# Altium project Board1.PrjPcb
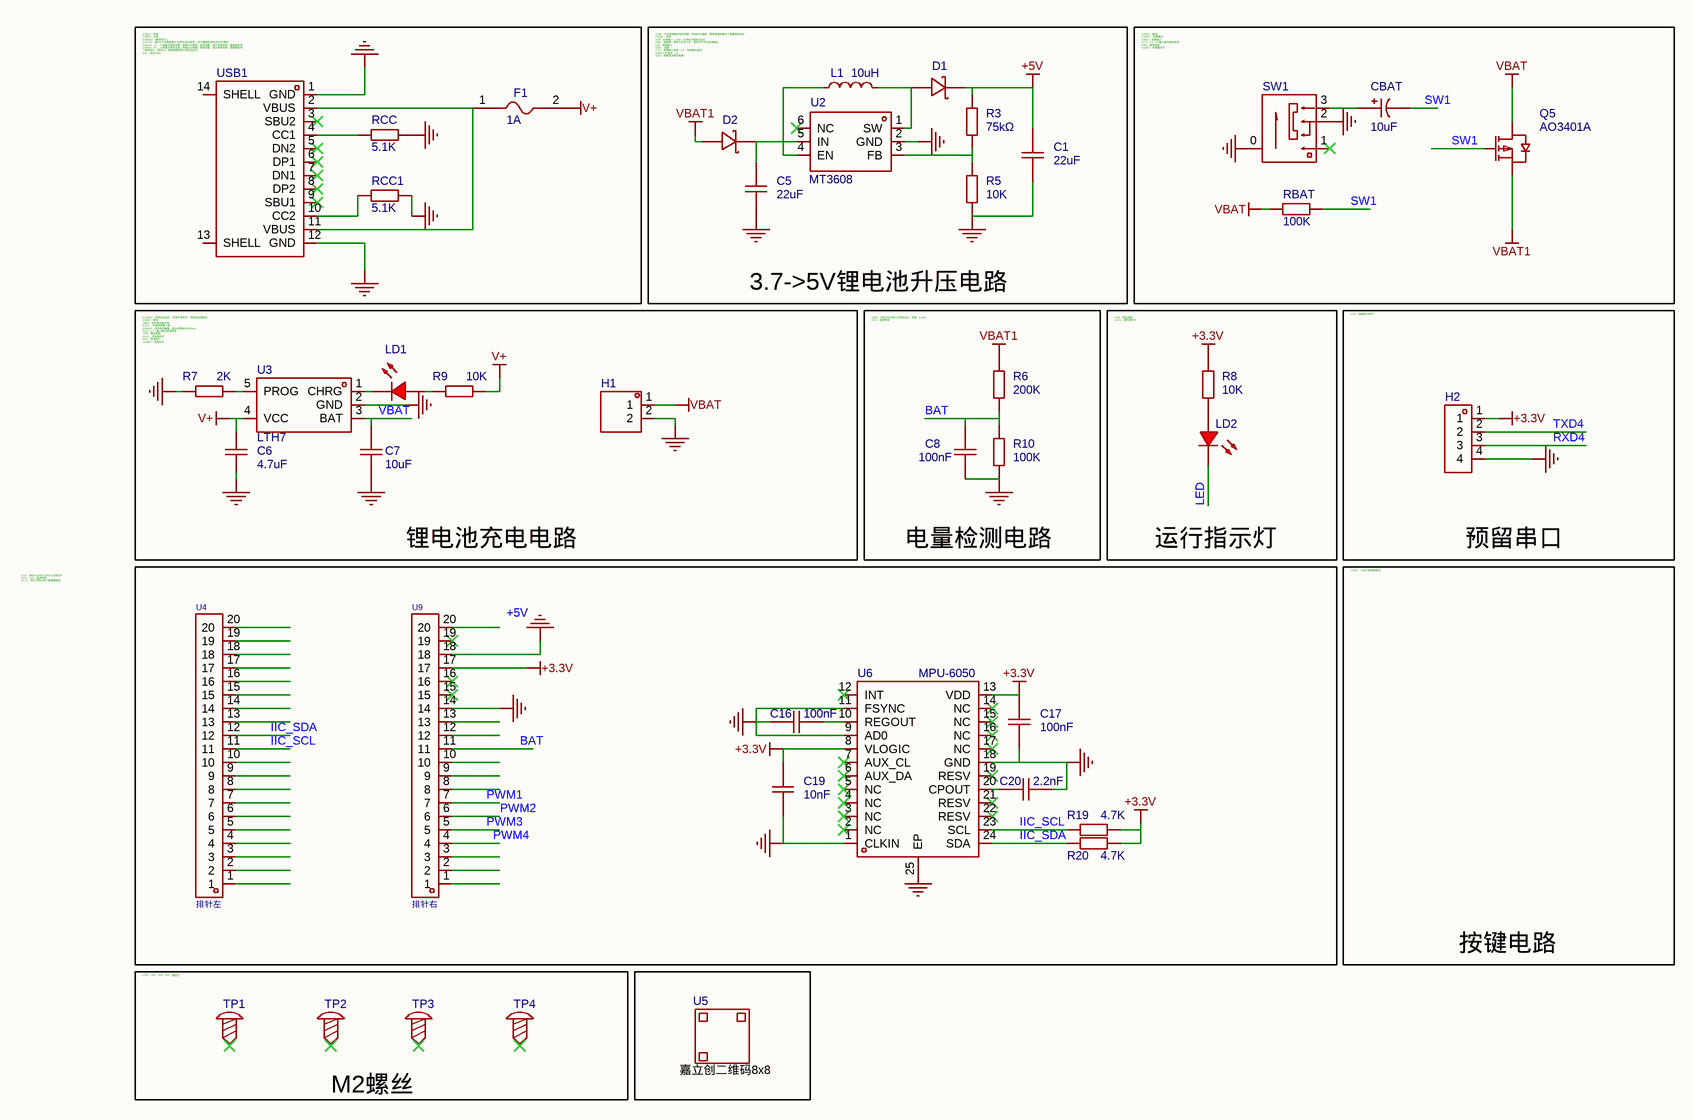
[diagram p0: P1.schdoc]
2 sheets, 63 parts. Net scope: global (net labels, ports and power ports of the same name join across sheets).
Board file: PCB1.pcbdoc
Sheets:
  P1.schdoc
  P2.schdoc

## Sheet P1.schdoc
size 420 x 297 mm; Symbol: Drawing-Symbol_A4; Company: 嘉立创EDA; Version: V1.0; Page Size: A4; @Project Name: fly_myself; @Update Date: 2026-09-26; @Create Date: 2026-09-26; Device: Drawing-Symbol_A4; @Board Name: Board1; @Page Name: P1; @Create Time: 16:50:29; @Page Count: 1; @Page No: 1; @Schematic Name: Schematic1; @Update Time: 16:50:29; @Assembly Variant: Basic; Border: 1; Title Block Position: 3; Size: A4; Width: 1655; Height: 1170; Region Start: 1; X Region Count: 6; Y Region Count: 4; Blade Width: 10

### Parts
C1  22uF  [C0805]
C5  22uF  [C0805]
C6  4.7uF  [C0603]
C7  10uF  [C0603]
C8  100nF  [C0603]
C16  100nF  [C0603]
C17  100nF  [C0603]
C19  10nF  [C0603]
C20  2.2nF  [C0603]
CBAT  10uF  [CAP-SMD_BD5.0-L5.3-W5.3-LS6.0-FD]
D1  1N5819WS  [SOD-323_L1.8-W1.3-LS2.5-RD]  (value not drawn)
D2  1N5819WS  [SOD-323_L1.8-W1.3-LS2.5-RD]  (value not drawn)
F1  Hold Current: 1A  [F1206]  (hidden comment: JK-nSMD100/16V)
H1  (no value)  [HDR-TH_2P-P2.54-V-M-1]
H2  (no value)  [HDR-TH_4P-P2.54-V-M]
L1  10uH  [IND-SMD_L2.5-W2.0]
LD1  (no value)  [LED_0603]
LD2  (no value)  [LED_0603]
Q5  AO3401A  [SOT-23_L2.9-W1.3-P1.90-LS2.4-BR]
R3  75kΩ  [R0603]
R5  10K  [R0603]
R6  200K  [R0603]
R7  2K  [R0603]
R8  10K  [R0603]
R9  10K  [R0603]
R10  100K  [R0603]
R19  4.7K  [R0603]
R20  4.7K  [R0603]
RBAT  100K  [R0603]
RCC  5.1K  [R0603]
RCC1  5.1K  [R0603]
SW1  SK-3296S-01-L1  [SW-SMD_3P-P1.50_L2.7-W6.6]  (value not drawn)
TP1  (no value)  [M2螺丝]
TP2  (no value)  [M2螺丝]
TP3  (no value)  [M2螺丝]
TP4  (no value)  [M2螺丝]
U2  MT3608  [SOT-23-6_L2.9-W1.6-P0.95-LS2.8-BL]
U3  LTH7  [SOT-23-5_L2.9-W1.6-P0.95-LS2.8-BR]
U4  排针左  [HDR-TH_LAIL-PM2.54-20P-L]
U5  (no value)  [JLC-QRCODE-8x8]
U6  MPU-6050  [QFN-24_L4.0-W4.0-P0.50-BL-EP2.7]
U9  排针右  [HDR-TH_LAIL-PM2.54-20P-L]
USB1  TYPE-C 16PIN 2MD(073)  [USB-C-SMD_TYPE-C-6PIN-2MD-073]  (value not drawn)

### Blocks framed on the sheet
3.7->5V锂电池升压电路: C1 C5 D1 D2 L1 R3 R5 U2
锂电池充电电路: C6 C7 H1 LD1 R7 R9 U3
电量检测电路: C8 R6 R10
运行指示灯: LD2 R8
预留串口: H2
M2螺丝: TP1-TP4

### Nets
+3.3V: C17.2 C19.2 H2.1 R8.2 R19.1 R20.1 U6.8(VLOGIC) U6.13(VDD) U9.17
+5V: C1.2 D1.1(K) R3.2
GND: C1.1 C5.1 C6.1 C7.1 C8.1 C16.1 C17.1 C19.1 C20.2 H1.2 H2.4 R5.1 R7.1 R10.1 RCC.2 RCC1.2 SW1.0 SW1.2 U2.2(GND) U3.2(GND) U6.1(CLKIN) U6.9(AD0) U6.11(FSYNC) U6.18(GND) U6.25(EP) U9.14 U9.18 USB1.1(GND) USB1.12(GND)
V+: C6.2 F1.2 R9.1 U3.4(VCC)
VBAT: C7.2 H1.1 Q5.3(D) RBAT.2 U3.3(BAT)
VBAT1: D2.2(A) Q5.2(S) R6.2
BAT: C8.2 R6.1 R10.2 U9.11
IIC_SCL: R19.2 U4.11 U6.23(SCL)
IIC_SDA: R20.2 U4.12 U6.24(SDA)
LED: LD2.1(C)
PWM1: U9.7
PWM2: U9.6
PWM3: U9.5
PWM4: U9.4
RXD4: H2.3
SW1: CBAT.2 Q5.1(G) RBAT.1
TXD4: H2.2
NetC5_2: C5.2 D2.1(K) L1.2 U2.4(EN) U2.5(IN)
NetC16_2: C16.2 U6.10(REGOUT)
NetC20_1: C20.1 U6.20(CPOUT)
NetCBAT_1: CBAT.1 SW1.3
NetD1_2: D1.2(A) L1.1 U2.1(SW)
NetF1_1: F1.1 USB1.2(VBUS) USB1.11(VBUS)
NetLD1_1: LD1.1(C) U3.1(CHRG)
NetLD1_2: LD1.2(A) R9.2
NetLD2_2: LD2.2(A) R8.1
NetR3_1: R3.1 R5.2 U2.3(FB)
NetR7_2: R7.2 U3.5(PROG)
NetRCC1_1: RCC1.1 USB1.10(CC2)
NetRCC_1: RCC.1 USB1.4(CC1)

Not connected (* = marked no-connect by the designer): SW1 1*; TP1 1*; TP2 1*; TP3 1*; TP4 1*; U2 6(NC)*; U4 1 2 3 4 5 6 7 8 9 10 13 14 15 16 17 18 19 20; U6 2(NC)* 3(NC)* 4(NC)* 5(NC)* 6(AUX_DA)* 7(AUX_CL)* 12(INT)* 14(NC)* 15(NC)* 16(NC)* 17(NC)* 19(RESV)* 21(RESV)* 22(RESV)*; U9 1 2 3 8 9 10 12 13 15* 16* 19* 20; USB1 3(SBU2)* 5(DN2)* 6(DP1)* 7(DN1)* 8(DP2)* 9(SBU1)* 13(SHELL) 14(SHELL)

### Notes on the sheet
- (near USB1) 1.GND：负极
  2.VBUS：正极
  3.SUB1/2：暂时用不上
  4.CC1/2：接10k下拉电阻用于支持PD协议供电，如不需要支持PD协议可悬空
  5.DN1/2：D-，USB差分信号负极，串接22Ω电阻，阻抗匹配，减少信号反射，提高稳定性
  6.DP1/2：D+，USB差分信号正极，串接22Ω电阻，阻抗匹配，减少信号反射，提高稳定性
  7.保险丝F1：限流1A，避免短路导致USB电流过大
  8.V+：电压为5V
- 1.SW：开关电源输出电压控制，内部MOS漏极，需将电感和整流二极管接到此处
  2.GND：接地
  3.FB：反馈输入，0.6V，R1和R5电阻分压点
  4.EN：使能端，高电平正常工作，低电平不升压直接输出
  5.IN：电源输入
  6.NC：空脚
  7.C5：电源输入滤波，C1：电源输出滤波
  8.设计工作电流：1A
  9.D2：控制电流单向导通
- (near SW1) 1.GND：接地
  2.VOUT：电源输出
  3.VDD：电源输入
  4.C2、C3、C4输入输出滤波电容
  5.R2：限流电阻
  6.LED1：电源指示灯
- 1.CHRG：充电状态指示，充电中低电平，充电完成高阻态
  2.GND：接地
  3.BAT：充电电流输出端
  4.VCC：外部电源输入端
  5.PROG：充电电流编程，接2k电阻时为500mA
  6.C6、C7：输入输出滤波电容
  7.R9：限流电阻
  8.LD1：充电指示灯
  9.H1：电池接口
  10.SW7：电源开关
- 1.BAT：电压为R6和R10电阻分压，范围：0~|.8V
  2.C8：滤波电容
- 1.R8：限流电阻
  2.LD2：通讯指示灯
- 1.H2：预留串口排针
- 1.U4：AI8051U/STC8051U主控芯片
  2.C9、C10：滤波电容
  3.C11：用于支持USB下载退耦电容
- 1.SW2：USB下载控制按钮
- 1.TP1、TP2、TP3、TP4：固定孔
- 按键电路
- Labels drawn without touching a wire or pin: +5V

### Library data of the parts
C1 C5 = CL21A226MAQNNNE: 容值:22uF;精度:±20%;额定电压:25V;材质(温度系数):X5R;; Manufacturer: SAMSUNG(三星); 3D Model: 1ba041120af144c991958decab20d241; 3D Model Transform: 78.74,51.181,0,0,0,0,0,0.0005,0; Tolerance: ±20%; Voltage Rated: 25V; Temperature Coefficient: X5R; AddInBom: yes; ModelName: C0805_L2.0-W1.3-H1.3
C6 = CL10A475KO8NNNC: 容值:4.7uF;精度:±10%;额定电压:16V;材质(温度系数):X5R;; Manufacturer: SAMSUNG(三星); 3D Model: ac125912035d415993ca9572d50418b1; 3D Model Transform: 62.992,31.496,0,0,0,0,0,0,0; Tolerance: ±10%; Voltage Rated: 16V; Temperature Coefficient: X5R; AddInBom: yes; ModelName: C0603_L1.6-W0.8-H0.8
C7 = CL10A106KP8NNNC: 容值:10uF;精度:±10%;额定电压:10V;材质(温度系数):X5R;; Manufacturer: SAMSUNG(三星); 3D Model: ac125912035d415993ca9572d50418b1; 3D Model Transform: 62.992,31.496,0,0,0,0,0,0,0; Tolerance: ±10%; Voltage Rated: 10V; Temperature Coefficient: X5R; AddInBom: yes; ModelName: C0603_L1.6-W0.8-H0.8
C8 = CAP_0603: Symbol: CapAcitance; 3D Model: ac125912035d415993ca9572d50418b1; 3D Model Transform: 62.992,31.496,0,0,0,0,0,0,0; ConvertToPcb: yes; ModelName: C0603_L1.6-W0.8-H0.8
C16 C17 C19 C20 = CAP_0603: Symbol: CapAcitance; Check: true; 3D Model: ac125912035d415993ca9572d50418b1; 3D Model Transform: 62.992,31.496,0,0,0,0,0,0,0; ConvertToPcb: yes; ModelName: C0603_L1.6-W0.8-H0.8
CBAT = JVJ50v10M5x5: 容值:10uF;精度:±20%;额定电压:50V;纹波电流:18mA@120Hz;; Manufacturer: JIERR(捷而瑞); 3D Model: ed942b427de741e3aabba01c64b2d7230819f05c4eef4c71ace90d822a990e87; 3D Model Transform: 236.22,208.661,0,0,0,0,-0.001,-0.003,0; Tolerance: ±20%; Voltage Rating: 50V; Lifetime: 2000hrs@105℃; AddInBom: yes
D1 D2 = 1N5819WS_C191023: 正向压降(Vf):600mV@1A;直流反向耐压(Vr):40V;平均整流电流(Io):1A;; Manufacturer: Hottech(合科泰); 3D Model: e9dd044ee7bf4221b3b795eb56bce7c0; 3D Model Transform: 98.91933,51.181,0,180,0,0,0.985,-0.0005,0; Reverse Voltage (Vr): 40V; Average Rectified Current (Io): 1A; AddInBom: yes; ModelName: SOD-323_L1.7-W1.3-H1.1-LS2.5
F1 = JK-nSMD100/16V: 最大电压:16V;最大电流:100A;保持电流:1A;跳闸电流:1.8A;; Manufacturer: JK(金科); 3D Model: f1628daad26847a79b887277a2bc8541; 3D Model Transform: 125.984,66.929,0,0,0,0,0,0,0; Operating Voltage (Max): 16V; Current Rating (Max): 100A; Trip Current: 1.8A; Resistance - Initial (Ri) (Min): 55mΩ; Resistance - Post Trip (R1) (Max): 330mΩ; Maximum Time to Trip: 300ms; AddInBom: yes; ModelName: F1206_L3.2-W1.7-H0.6
H1 = HDR-M_2.54_1x2P: Manufacturer: Ckmtw(灿科盟); Manufacturer Part: B-2100S02P-A110; Symbol: 210S-1*2P L=11.6MMGold-plated black; 3D Model: 79b2e9f2d70a4d68a1b7098f27c6d4c5; 3D Model Transform: 200,100,0,0,0,0,0,0,-118.11; ConvertToPcb: yes; ModelName: HDR-M-2.54_1x2
H2 = HDR-M_2.54_1x4P: Symbol: PZ254V-11-04P; 3D Model: 112f4d05e8d64e99ab9a333894bea4f9; 3D Model Transform: 399.999,104.7242,0,0,0,0,0,0,-118.11; ConvertToPcb: yes; ModelName: HDR-TH_4P-P2.54-M-LI-1X4P
L1 = FTC252012S100MBCA: 电感值:10uH;精度:±20%;额定电流:1.2A;饱和电流(Isat):1.6A;类型:一体成型电感;; Manufacturer: cjiang(长江微电); 3D Model: 85d117b4abb34d9087271edcd9ba0330; 3D Model Transform: 99.2124,78.74,0,0,0,0,0,0,0; Tolerance: ±20%; Rated Current: 1.2A; Saturation Current (Isat): 1.6A; DC Resistance (DCR): 330mΩ; Type: 一体成型电感; AddInBom: yes; ModelName: IND-SMD_L2.5-W2.0-H1.2
LD1 LD2 = LED_0603-R: Symbol: LED_R; Convert to PCB: yes; 3D Model: dd8257b0d61a4cd7b68939a056e08095; 3D Model Transform: 58.72,29.4,22.03,0,0,0,0,0,0; ModelName: LED-0603_R
Q5 = AO3401A_C347476: 数量:1个P沟道;漏源电压(Vdss):30V;连续漏极电流(Id):4.2A;导通电阻(RDS(on)):50mΩ@10V;耗散功率(Pd):1.4W;阈值电压(Vgs(th)):1.3V;; Manufacturer: UMW(友台半导体); 3D Model: c62791f0466c4ae2a892c056b845b0ca0819f05c4eef4c71ace90d822a990e87; 3D Model Transform: 98.64468,114.173,0,180,0,0,0.001,-0.002,0; Number: 1个P沟道; Drain to Source Voltage: 30V; Current - Continuous Drain(Id): 4.2A; Pd - Power Dissipation: 1.4W; Gate Threshold Voltage (Vgs(th)): 1.3V; Gate Charge(Qg): 9.4nC@4.5V; Input Capacitance(Ciss): 954pF; Reverse Transfer Capacitance (Crss@Vds): 77pF; Type: P沟道; Output Capacitance(Coss): 115pF; AddInBom: yes; ModelName: SOT-23-3P_L2.9-W1.3-H1.0-LS2.4-P0.95
R3 = 0603WAF7502T5E: 电阻类型:厚膜电阻;阻值:75kΩ;精度:±1%;功率:100mW;工作电压:75V;温度系数:±100ppm/℃;; Manufacturer: UNI-ROYAL(厚声); 3D Model: fc143cca1e79419f9cd78b61e9279f080819f05c4eef4c71ace90d822a990e87; 3D Model Transform: 31.8897,63.7794,0,90,0,0,0,0,0; Tolerance: ±1%; Power(Watts): 100mW; Voltage-Supply(Max): 75V; AddInBom: yes
R5-R10 = Res_0603: Symbol: 电阻; 3D Model: fc143cca1e79419f9cd78b61e9279f08; 3D Model Transform: 31.8897,63.7794,0,90,0,0,0,0,0; ConvertToPcb: yes
R19 R20 = Res_0603: Symbol: 电阻; Check: true; 3D Model: fc143cca1e79419f9cd78b61e9279f08; 3D Model Transform: 31.8897,63.7794,0,90,0,0,0,0,0; ConvertToPcb: yes
RBAT RCC RCC1 = Res_0603: Symbol: 电阻; 3D Model: fc143cca1e79419f9cd78b61e9279f080819f05c4eef4c71ace90d822a990e87; 3D Model Transform: 31.8897,63.7794,0,90,0,0,0,0,0; ConvertToPcb: yes
SW1 = SK-3296S-01-L1: 电路结构:单刀双掷;安装方式:卧贴;开关颜色:黑色;额定电流(DC):50mA;额定电压(DC):12V;额定电流(AC):50mA;额定电压(AC):12V;机械寿命:1万次;; Manufacturer: XKB Connectivity(中国星坤); 3D Model: fac986d38b354d44b3f0357550471109; 3D Model Transform: 307.086,204.724,0,180,0,0,0,-28.898,-19.685; Circuit: 单刀双掷; Actuator Style: 矩形柱状; Pin Style: SMD接片; Switch Length: 7.8mm; Switch Width: 2.75mm; Switch Height: 1.35mm; Actuator Color: 黑色; Current Rating (DC): 50mA; Voltage Rating (DC): 12V; Mechanical Life: 1万次; AddInBom: yes; ModelName: SW-SMD_3P-L6.6-W2.7-LS7.8-P1.50
TP1-TP4 = M2螺丝: Symbol: 螺丝孔; ConvertToPcb: yes
U2 = MT3608: 功能类型:升压型;输入电压:2V~24V;输出电压:28V;输出电流(最大值):-;; Manufacturer: 西安航天民芯; 3D Model: 18da8f6c14a34920b3e136b5c401a119; 3D Model Transform: 110.236,113.364,0,90,0,0,0.0005,0.0005,0; Function: 升压型; Input Voltage: 2V~24V; Output Voltage: 28V; Switching Frequency: 1.2MHz; Number of Outputs: 1; Topology: 升压式; Switch tube (built-in/external): 内置; AddInBom: yes; ModelName: SOT-23-6_L2.9-W1.6-H1.5-LS2.8-P0.95
U3 = LTH7_C5342381: Manufacturer: TECH PUBLIC(台舟); 3D Model: 7ba65df16e7b4570af156e925f9c37fe; 3D Model Transform: 114.173,114.173,0,90,0,0,0,0,0; AddInBom: yes
U4 U9 = LAIL-PM2.54-20P-L: 插孔结构:1x20P;间距:2.54mm;圆孔/方孔:方孔;安装方式:直插;排数:单排;总孔位数:20P;额定电流:3A;额定电压:250V;插孔方向:顶部;塑高:8.5mm;触头材质:黄铜;触头镀层:金;工作温度:-25℃~+80℃;; Manufacturer: LAILAN(莱联); Holes Structure: 1x20P; Pitch: 2.54mm; Circular Hole / Square Hole: 方孔; Number of Positions: 20P; Current Rating: 3A; Voltage Rating (Max): 250V; Holes Direction: 顶部; PIN Length: 3mm; AddInBom: yes
U5 = 嘉立创二维码8x8: Check: true; AddInBom: yes
U6 = MPU-6050: 传感器类型:加速度计陀螺仪;; Manufacturer: TDK InvenSense(应美盛); Symbol: MPU-6050_C24112; Check: true; 3D Model: 78358972877945cb927aaf48cb6c1c63; 3D Model Transform: 158.267,158.267,0,0,0,0,0,0,0; AddInBom: yes
USB1 = TYPE-C 16PIN 2MD(073): 连接器类型:Type-C;标准:-;公母:母;端口数量:1;触点数量:16P;安装方式:卧贴;额定电流 - 电源:5A;工作温度范围:-25℃~+85℃;; Manufacturer: SHOU HAN(首韩); 3D Model: 3a41b9ec9b654a0fad4d118405ec6290; 3D Model Transform: 351.9678,298.4246,0,0,0,0,0,-47.244,-35.433; Gender: 母; Number of Ports: 1; Number of Contacts: 16P; Current Rating - Power (Max): 5A; AddInBom: yes

## Sheet P2.schdoc
size 297 x 209 mm; Symbol: Drawing-Symbol_A4; Device: Drawing-Symbol_A4; Company: 嘉立创EDA; Version: V1.0; Page Size: A4; @Project Name: fly_myself; @Update Date: 2026-09-26; @Create Date: 2026-09-26; @Board Name: Board1; @Page Name: P2; @Create Time: 10:33:04; @Page Count: 1; @Page No: 0; @Schematic Name: Schematic1; @Update Time: 10:33:04; @Assembly Variant: Basic; Border: 1; Title Block Position: 3; Size: A4; Width: 1170; Height: 825; Region Start: 1; X Region Count: 6; Y Region Count: 4; Blade Width: 10
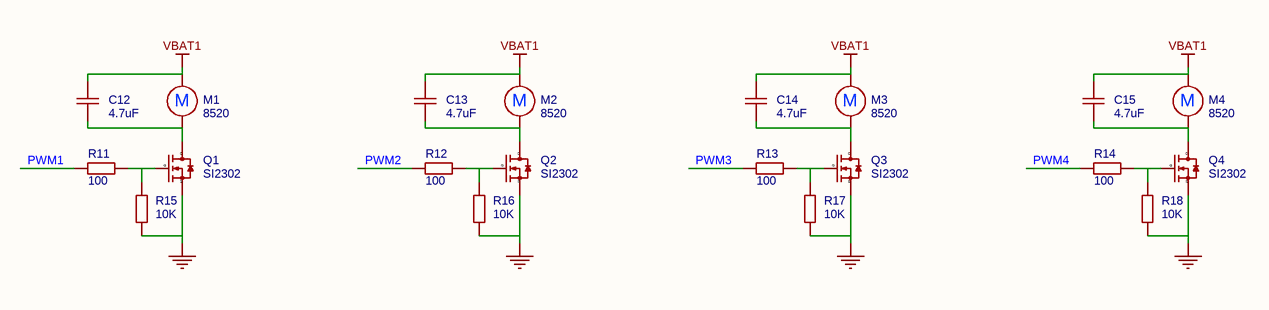
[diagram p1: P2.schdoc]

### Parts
C12  4.7uF  [C0603]
C13  4.7uF  [C0603]
C14  4.7uF  [C0603]
C15  4.7uF  [C0603]
M1  8520  [8520电机接口]
M2  8520  [8520电机接口]
M3  8520  [8520电机接口]
M4  8520  [8520电机接口]
Q1  SI2302  [SOT-23-3_L2.9-W1.3-P1.90-LS2.4-BR]
Q2  SI2302  [SOT-23-3_L2.9-W1.3-P1.90-LS2.4-BR]
Q3  SI2302  [SOT-23-3_L2.9-W1.3-P1.90-LS2.4-BR]
Q4  SI2302  [SOT-23-3_L2.9-W1.3-P1.90-LS2.4-BR]
R11  100  [R0603]
R12  100  [R0603]
R13  100  [R0603]
R14  100  [R0603]
R15  10K  [R0603]
R16  10K  [R0603]
R17  10K  [R0603]
R18  10K  [R0603]

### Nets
GND: Q1.2(S) Q2.2(S) Q3.2(S) Q4.2(S) R15.1 R16.1 R17.1 R18.1
VBAT1: C12.2 C13.2 C14.2 C15.2 M1.1 M2.1 M3.1 M4.1
PWM1: R11.2
PWM2: R12.2
PWM3: R13.2
PWM4: R14.2
NetC12_1: C12.1 M1.2 Q1.3(D)
NetC13_1: C13.1 M2.2 Q2.3(D)
NetC14_1: C14.1 M3.2 Q3.3(D)
NetC15_1: C15.1 M4.2 Q4.3(D)
NetQ1_1: Q1.1(G) R11.1 R15.2
NetQ2_1: Q2.1(G) R12.1 R16.2
NetQ3_1: Q3.1(G) R13.1 R17.2
NetQ4_1: Q4.1(G) R14.1 R18.2

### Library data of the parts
C12-C15 = CL10A475KO8NNNC: as C6 on sheet P1
M1-M4 = 716电机接口: Check: true; AddInBom: yes
Q1-Q4 = SI2302_C181087: 类型:1个N沟道;漏源电压(Vdss):20V;连续漏极电流(Id):2.1A;功率(Pd):400mW;导通电阻(RDS(on)@Vgs,Id):72mΩ@4.5V,3.6A;阈值电压(Vgs(th)@Id):1.2V@50uA;; Manufacturer: Hottech(合科泰); Check: true; 3D Model: c62791f0466c4ae2a892c056b845b0ca; 3D Model Transform: 98.425,114.173,0,180,0,0,0.0005,-0.0005,0; Type: 1个N沟道; Drain Source Voltage (Vdss): 20V; Continuous Drain Current (Id): 2.1A; Power Dissipation (Pd): 400mW; AddInBom: yes; ModelName: SOT-23-3P_L2.9-W1.3-H1.0-LS2.4-P0.95
R11-R18 = Res_0603: as R19 on sheet P1

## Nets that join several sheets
GND: P1 (29 pins), P2 (8 pins)
VBAT1: P1 (D2.2 Q5.2 R6.2), P2 (8 pins)
PWM1: P1 (U9.7), P2 (R11.2)
PWM2: P1 (U9.6), P2 (R12.2)
PWM3: P1 (U9.5), P2 (R13.2)
PWM4: P1 (U9.4), P2 (R14.2)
